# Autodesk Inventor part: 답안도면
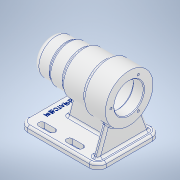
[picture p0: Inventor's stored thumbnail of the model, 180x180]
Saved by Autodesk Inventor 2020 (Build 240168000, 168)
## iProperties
Created: 2021-10
Part Number: 답안도면
Material: 알루미늄 6061
Document SubType Name: Modeling
Designer: user
Density: 2.7 g/cm^3
Appearance: 알루미늄 - 평지
Mass: 693.151 g
Surface Area: 698.728 cm^2
Volume: 256.723 cm^3
Author: user
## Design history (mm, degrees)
sketch "스케치1"
  geometry: L1 (0, 0)-(0, 34); L2 (0, 34)-(-32, 34); L3 (-32, 34)-(-32, 30); L4 (-32, 30)-(-66, 30); L5 (-66, 30)-(-66, 27); L6 (-66, 27)-(-88, 27); L7 (-88, 27)-(-88, 25); L8 (-88, 25)-(-112, 25); L9 (-112, 25)-(-112, 0); L10 (-112, 0)-(0, 0)
  constraints: 20 end point, 9 perpendicular, 1 vertical
  dimensions: "d0" = 24 distance of L7.end L8.end; "d1" = 46 distance between parallel lines of L5 L9; "d2" = 80 distance between parallel lines of L3 L9; "d3" = 112 distance between parallel lines of L1 L9; "d4" = 50 diameter of L8 L10; "d5" = 54 diameter of L6 L10; "d6" = 60 diameter of L4 L10; "d7" = 68 diameter of L2 L10
revolve "회전1" sketch "스케치1" stored, may be unused: angle "d8" = 90 deg
sketch "스케치2"
  geometry: C1 r 21 at (0, 0); 1 further point
  constraints: 1 centre point, 1 coincident
  dimensions: "d9" = 42 diameter of C1
extrude "돌출1" cut sketch "스케치2" distance "d10" = 15; taper "d11" = 0 deg
sketch "스케치3"
  geometry: C1 r 24 at (0, 0); 1 further point
  constraints: 1 centre point, 1 coincident
  dimensions: "d12" = 48 diameter of C1
extrude "돌출2" cut sketch "스케치3" distance "d13" = 54; taper "d14" = 0 deg
sketch "스케치4"
  geometry: C1 r 21 at (0, 0); 1 further point
  constraints: 1 centre point, 1 coincident
  dimensions: "d15" = 42 diameter of C1
extrude "돌출3" cut sketch "스케치4" distance "d16" = 12; taper "d17" = 0 deg
sketch "스케치5"
  geometry: C1 r 24 at (0, 0) reference; C2 r 17.5 at (0, 0); 1 further point
  constraints: 1 centre point, 1 coincident
  dimensions: "d18" = 35 diameter of C2
extrude "돌출4" cut sketch "스케치5" distance "d19" = 18; taper "d20" = 0 deg
sketch "스케치6"
  geometry: C1 r 16 at (0, 0); 1 further point
  constraints: 1 centre point, 1 coincident
  dimensions: "d21" = 32 diameter of C1
extrude "돌출5" cut sketch "스케치6" distance "d22" = 4; taper "d23" = 0 deg
sketch "스케치7"
  geometry: C1 r 21 at (0, 0) reference; C2 r 10.5 at (0, 0); 1 further point
  constraints: 1 centre point, 1 coincident
  dimensions: "d24" = 21 diameter of C2
extrude "돌출6" cut sketch "스케치7" distance "d25" = 3; taper "d26" = 0 deg
node "작업 평면1"
sketch "스케치10"
  geometry: L1 (112, 45)-(0, 45); L2 (0, 45)-(0, -45); L3 (0, -45)-(112, -45); L4 (112, -45)-(112, 45); L5 (112, 45)-(0, -45); L6 (0, 45)-(112, -45); L7 (112, 25)-(112, -25) reference; 3 further points
  constraints: 12 end point, 3 midpoint, 2 parallel, 1 horizontal, 1 horizontal alignment, 1 perpendicular, 1 point on line
  dimensions: "d28" = 112 distance of L3.end L2.end; "d29" = 90 distance of L2.end L1.end
extrude "돌출7" join sketch "스케치10" distance "d30" = 8; taper "d31" = 0 deg
sketch "스케치11"
  geometry: L1 (-85, -4)-(-8, -4); L2 (-8, -4)-(-8, 4); L3 (-8, 4)-(-85, 4); L4 (-85, 4)-(-85, -4); L5 (-85, -4)-(-8, 4); L6 (-8, -4)-(-85, 4); L7 (-112, -45)-(0, -45) reference; L8 (0, -45)-(0, 45) reference; 4 further points
  constraints: 12 end point, 4 midpoint, 2 parallel, 1 horizontal, 1 horizontal alignment, 1 perpendicular
  dimensions: "d34" = 8 distance between parallel lines of L8 L2; "d35" = 8 distance of L3.end L1.start; "d36" = 77 distance of L2.end L3.end
extrude "돌출8" join sketch "스케치11" stored distance "d37" = 8; taper "d38" = 0 deg
sketch "스케치12"
  geometry: L1 (-41, -8)-(-41, 0) reference; L2 (-41, 0)-(0, 0) reference; L3 (0, 0)-(0, 28.236) reference; L4 (8, 28.236)-(8, 0) reference; L5 (8, 0)-(49, 0) reference; L6 (49, 0)-(49, -8) reference; L7 (49, -8)-(-41, -8) reference; L8 (0, 0)-(8, 0) reference; L9 (-19.409, 37.342)-(-33, 0); L10 (49, 0)-(-41, 0) reference; C1 r 21 at (4, 62) reference; A1 r 34 centre (4, 62) between (8, 28.236) and (0, 28.236) reference; A2 r 34 centre (4, 62) between (0, 28.236) and (8, 28.236) reference; 2 further points
  constraints: 2 end point, 1 point on circle, 1 point on line
  dimensions: "d39" = 8 distance from line of L1 L9.end; "d40" = 110 deg angle of L2 L9
extrude "돌출9" join sketch "스케치12" distance "d41" = 8; taper "d42" = 0 deg
sketch "스케치14"
  geometry: L1 (-92, 33)-(-77, 33); L2 (-92, 28.5)-(-77, 28.5); L3 (-77, 37.5)-(-92, 37.5); L4 (-112, 45)-(-112, -45) reference; L5 (-52, 33)-(-37, 33); L6 (-52, 28.5)-(-37, 28.5); L7 (-37, 37.5)-(-52, 37.5); A1 r 4.5 centre (-92, 33) between (-92, 37.5) and (-92, 28.5); A2 r 4.5 centre (-77, 33) between (-77, 28.5) and (-77, 37.5); A3 r 4.5 centre (-52, 33) between (-52, 37.5) and (-52, 28.5); A4 r 4.5 centre (-37, 33) between (-37, 28.5) and (-37, 37.5); 3 further points
  constraints: 16 end point, 8 point on circle, 8 tangent, 4 centre point, 2 horizontal, 2 midpoint, 2 parallel
  dimensions: "d43" = 9 diameter of A2; "d44" = 20 distance from line of L1.start L4; "d45" = 15 distance of L1.end L1.start; "d46" = 9 diameter of A4; "d47" = 25 distance of L5.start L1.end; "d48" = 15 distance of L5.end L5.start; "d49" = 33 vertical distance of point (0, 0) point (-84.5, 33); "d50" = 33 vertical distance of point (0, 0) point (-44.5, 33)
extrude "돌출10" cut sketch "스케치14" distance "d51" = 30; taper "d52" = 0 deg
sketch "스케치16"
  geometry: C1 r 10.5 at (0, 0) reference; 2 further points
  constraints: 1 horizontal alignment
  dimensions: "d54" = 26 distance of point (0, 0) point (-26, 0)
hole "구멍1" sketch "스케치16" at (-26, 0) diameter "d55" = 3.242; stored, may be unused: countersink angle "d59" = 90 deg, drill point angle "d61" = 118 deg; dims "d56" = 8, "d57" = 4, "d58" = 2, "d60" = 11
chamfer "모따기1" distance "d65" = 1; stored, may be unused: second distance "d66" = 2, angle "d67" = 45 deg
fillet "모깎기1" dims "d68" = 3
fillet "모깎기2" dims "d69" = 0.3
fillet "모깎기3" dims "d70" = 3
fillet "모깎기4" dims "d71" = 8
fillet "모깎기5" dims "d72" = 3
feature "면 기울기1" dims angle "d73" = 15 deg
fillet "모깎기6" dims "d74" = 12
fillet "모깎기7" dims "d75" = 3
fillet "모깎기8" dims "d76" = 3
fillet "모깎기9" dims "d77" = 3
sketch "스케치17"
  geometry: L1 (-112, 33)-(-112, -33) reference; 2 further points
  constraints: 1 horizontal alignment, 1 other
  dimensions: "d78" = 12 distance from line of point (-100, 0) L1
feature "엠보싱1" sketch "스케치17" dims "d0" = 24, "d1" = 46, "d2" = 80, "d3" = 112, "d4" = 50, "d5" = 54, "d6" = 60, "d7" = 68, "d79" = 0.5, "d80" = 0
fillet "모깎기10" dims "d81" = 3
node "솔리드1"
mirror "미러1"
mirror "미러2"
pattern_circular "원형 패턴1" dims angle "d63" = 360 deg
node "절단 모서리 투영1"
feature "A9D066F2-1C7D-4E18-AEED-F7BC21143FA4" dims "d55" = 3.242, "d56" = 8, "d57" = 4, "d58" = 2, "d59" = 90 deg, "d60" = 11, "d61" = 118 deg
